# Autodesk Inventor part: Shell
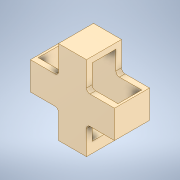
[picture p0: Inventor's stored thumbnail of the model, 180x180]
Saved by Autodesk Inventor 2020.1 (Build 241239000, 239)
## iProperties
Created: 2019-10
Part Number: Shell
Material: Polyethylene, Low Density
Document SubType Name: Modeling
Designer: Synergysoft Dell02
Density: 0.894 g/cm^3
Appearance: Smooth - Off-White
Author: Synergysoft Dell02
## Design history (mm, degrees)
sketch "Sketch1"
  geometry: L1 (-20, 60)-(20, 60); L2 (20, 60)-(20, -60); L3 (20, -60)-(-20, -60); L4 (-20, -60)-(-20, 60); L5 (-20, 60)-(20, -60); L6 (20, 60)-(-20, -60); L7 (-60, 20)-(60, 20); L8 (60, 20)-(60, -20); L9 (60, -20)-(-60, -20); L10 (-60, -20)-(-60, 20); L11 (-60, 20)-(60, -20); L12 (60, 20)-(-60, -20); 5 further points
  constraints: 24 end point, 4 midpoint, 4 parallel, 2 horizontal, 2 perpendicular
  dimensions: "d0" = 40 distance of L2.end L3.end; "d1" = 120 distance of L1.end L2.end (= d2); "d2" = 120 distance of L8.end L9.end; "d3" = 40 distance of L7.end L8.end (= d0)
extrude "Extrusion1" new body sketch "Sketch1" stored distance "d4" = 50; taper "d5" = 0 deg
shell "Shell2" dims "d25" = 8, "d27" = 15, "d28" = 3
fillet "Fillet2" dims "d26" = 5
fillet "Fillet1" dims "d7" = 5
shell "Shell1" dims "d6" = 5, "d8" = 10, "d9" = 3
body "Solid1"
